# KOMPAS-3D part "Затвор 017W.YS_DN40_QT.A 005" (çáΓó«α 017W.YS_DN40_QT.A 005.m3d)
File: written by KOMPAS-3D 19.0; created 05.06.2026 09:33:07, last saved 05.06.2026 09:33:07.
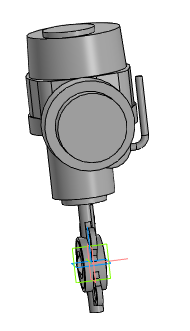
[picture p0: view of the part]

Document properties: Автор: Энергия; Полное имя файла: ..\..\..\3d для проектировщиков\x.x Тип 017W.Y(S) Затвор дисковый поворотный межфланцевый\Затвор 017W.Y(S)_DN32-DN1200_QT.A_MT903.A\Затвор 017W.YS_DN40_QT.A 005.a3d

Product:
- Part/product: Затвор 017W.YS_DN40_QT.A 005
    Масса: 37.5305

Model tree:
1. Операция без истории:1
